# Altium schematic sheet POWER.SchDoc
size A4
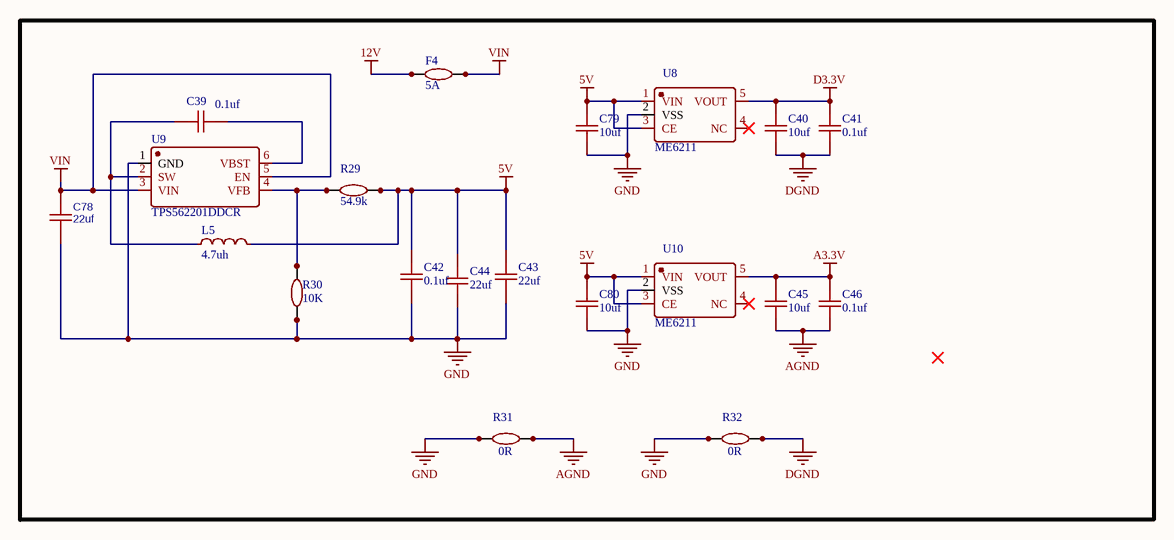
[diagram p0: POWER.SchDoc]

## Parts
C39  0.1uf  [C0603]
C40  10uf  [C0603]
C41  0.1uf  [C0603]
C42  0.1uf  [C0603]
C43  22uf  [C0805]
C44  22uf  [C0805]
C45  10uf  [C0603]
C46  0.1uf  [C0603]
C78  22uf  [C0805]
C79  10uf  [C0603]
C80  10uf  [C0603]
F4  5A  [R1206]
L5  4.7uh  [L-0420]
R29  54.9k  [R0603]
R30  10K  [R0603]
R31  0R  [R0603]
R32  0R  [R0603]
U8  ME6211  [SOT-23-5]
U9  TPS562201DDCR  [SOT-23-6]
U10  ME6211  [SOT-23-5]

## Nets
5V: C42.1 C43.1 C44.1 C79.1 C80.1 L5.2 R29.1 U8.1(VIN) U8.3(CE) U10.1(VIN) U10.3(CE)
12V: F4.1
A3.3V: C45.2 C46.2 U10.5(VOUT)
AGND: C45.1 C46.1 R31.1
D3.3V: C40.1 C41.1 U8.5(VOUT)
DGND: C40.2 C41.2 R32.1
GND: C42.2 C43.2 C44.2 C78.2 C79.2 C80.2 R30.2 R31.2 R32.2 U8.2(VSS) U9.1(GND) U10.2(VSS)
VIN: C78.1 F4.2 U9.3(VIN) U9.5(EN)
NetC39_1: C39.1 U9.6(VBST)
NetC39_2: C39.2 L5.1 U9.2(SW)
NetR29_2: R29.2 R30.1 U9.4(VFB)

Not connected (* = marked no-connect by the designer): U8 4(NC)*; U10 4(NC)*

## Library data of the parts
C39-C46 C79 C80 = 贴片电容
C78 = 1n: nameAlias: Value(F); Contributor: LCEDA_Lib
F4 R29-R32 = 贴片电阻
L5 = 贴片电感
